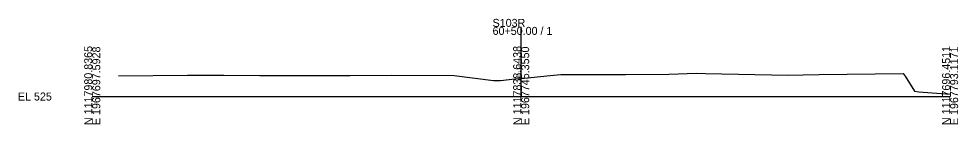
# Model space of a CAD drawing. Extents: x 974 to 1303, y 990 to 10019.
# Drawn here: x 974.3 to 1302.8, y 2990.3 to 3027.2 of the extents above; entities that cross this region are included whole.
import ezdxf

# ---------------------------------------------------------------- set-up
doc = ezdxf.new("R2010")
doc.units = 0
for name, color, linetype in [('Level 10', 7, 'Continuous'), ('Level 60', 7, 'Continuous'), ('Level 63', 7, 'Continuous')]:
    doc.layers.add(name, color=color, linetype=linetype)

msp = doc.modelspace()

# ---------------------------------------------------------------- linework, layer by layer
at = {"layer": 'Level 60'}
for p, q in [((1009.19, 3007.28), (1033.26, 3007.44)), ((1033.26, 3007.44), (1046.04, 3007.5)), ((1046.04, 3007.5), (1058.65, 3007.37)), ((1058.65, 3007.37), (1090.25, 3007.3)), ((1090.25, 3007.3), (1104.6, 3007.51)), ((1104.6, 3007.51), (1126.61, 3007.4)), ((1126.61, 3007.4), (1140.37, 3005.66)), ((1142.77, 3005.59), (1147.8, 3006.13)), ((1147.8, 3006.13), (1150, 3006.34)), ((1150, 3006.34), (1160.13, 3007.34)), ((1160.13, 3007.34), (1163.89, 3007.76)), ((1163.89, 3007.76), (1186.5, 3007.66)), ((1186.5, 3007.66), (1201.67, 3007.83)), ((1201.67, 3007.83), (1211.31, 3008.12)), ((1211.31, 3008.12), (1214.42, 3008)), ((1214.42, 3008), (1243.27, 3007.46)), ((1243.27, 3007.46), (1248.67, 3007.62)), ((1248.67, 3007.62), (1254.17, 3007.68)), ((1254.17, 3007.68), (1283.64, 3008)), ((1283.64, 3008), (1284.33, 3007.09)), ((1284.33, 3007.09), (1287.5, 3001.83)), ((1140.37, 3005.66), (1140.89, 3005.65)), ((1140.89, 3005.65), (1141.62, 3005.58)), ((1141.62, 3005.58), (1142.77, 3005.59)), ((1287.5, 3001.83), (1289.11, 3001.68)), ((1289.11, 3001.68), (1300, 3000.88))]:
    msp.add_line(p, q, dxfattribs=at)
at = {"layer": 'Level 63'}
for p, q in [((1150, 3000), (1150, 3024.36)), ((1000, 3000), (1150, 3000)), ((1150, 3000), (1300, 3000))]:
    msp.add_line(p, q, dxfattribs=at)

# ---------------------------------------------------------------- texts
at = {"layer": 'Level 10'}
msp.add_text('531.34', height=0.9, rotation=90, dxfattribs=at).set_placement((1149.95, 3006.84))
at = {"layer": 'Level 63'}
for s, p in [('S103R', (1140, 3024.36)), ('60+50.00 / 1', (1140, 3021.56)), ('EL 525', (974, 2998.6))]:
    msp.add_text(s, height=2.8, dxfattribs=at).set_placement(p)
for s, p in [('N 1117980.8365', (1000, 2990)), ('E 1967697.5928', (1002.8, 2990)), ('N 1117838.6438', (1150, 2990)), ('E 1967745.3550', (1152.8, 2990)), ('N 1117696.4511', (1300, 2990)), ('E 1967793.1171', (1302.8, 2990))]:
    msp.add_text(s, height=2.8, rotation=90, dxfattribs=at).set_placement(p)

doc.saveas('drawing.dxf')
